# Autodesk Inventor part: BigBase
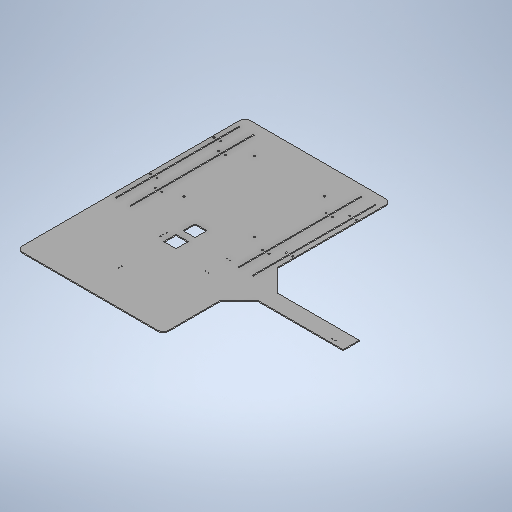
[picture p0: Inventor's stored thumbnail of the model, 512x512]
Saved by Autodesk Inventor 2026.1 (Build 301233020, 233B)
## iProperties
Created: 2026-10
Part Number: BigBase
Material: Generic
Document SubType Name: Modeling
Designer: hp
Density: 1 g/cm^3
Appearance: Default
Author: hp
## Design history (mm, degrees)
sketch "BigBaseSketch"
  geometry: L1 (0, 0)-(1200, 0); L2 (1200, 0)-(1200, 770); L3 (1200, 770)-(0, 770); L4 (0, 770)-(0, 0); L5 (150, 200)-(520, 570); L6 (520, 200)-(150, 570); C1 r 5 at (520, 200); C2 r 5 at (520, 570); C3 r 5 at (150, 200); C4 r 5 at (150, 570); 2 further points
  constraints: 12 end point, 4 centre point, 2 horizontal alignment, 2 midpoint, 2 parallel, 2 vertical alignment, 1 horizontal, 1 perpendicular
  dimensions: "d0" = 1200 distance of L3.end L2.end; "d4" = 10 diameter of C1 (= d10); "d8" = 10 diameter of C2 (= d10); "d9" = 370 distance of L5.end L6.start (= d12); "d10" = 10 diameter of C3; "d11" = 10 diameter of C4; "d12" = 370 distance of L6.end L5.start; "d13" = 370 distance of L6.end L5.end (= d9); "d39" = 200 distance from line of L5.start L1
extrude "Extrusion2" new body sketch "BigBaseSketch" distance "d14" = 5; taper "d15" = 0 deg
sketch "StorageAreaSketch"
  geometry: L1 (435, 205)-(515, 205); L2 (515, 205)-(515, 285); L3 (515, 285)-(435, 285); L4 (435, 295)-(515, 295); L5 (345, 205)-(425, 205); L6 (435, 285)-(435, 205); L7 (425, 205)-(425, 285); L8 (345, 285)-(345, 205); L9 (425, 285)-(345, 285); L10 (515, 295)-(515, 375); L11 (515, 375)-(435, 375); L12 (345, 295)-(425, 295); L13 (435, 395)-(515, 395); L14 (345, 375)-(345, 295); L15 (425, 375)-(345, 375); L16 (245, 285)-(245, 205); L17 (435, 475)-(435, 395); L18 (425, 475)-(345, 475); L19 (325, 375)-(245, 375); L20 (235, 205)-(235, 285); L21 (245, 205)-(325, 205); L22 (325, 205)-(325, 285); L23 (325, 285)-(245, 285); L24 (155, 295)-(235, 295); L25 (155, 205)-(235, 205); L26 (235, 285)-(155, 285); L27 (155, 285)-(155, 205); L28 (155, 375)-(155, 295); L29 (155, 485)-(235, 485); L30 (235, 485)-(235, 565); L31 (235, 565)-(155, 565); L32 (155, 565)-(155, 485); L33 (345, 475)-(345, 395); L34 (325, 295)-(325, 375); L35 (245, 375)-(245, 295); L36 (245, 295)-(325, 295); L37 (235, 295)-(235, 375); L38 (345, 395)-(425, 395); L39 (425, 295)-(425, 375); L40 (135, 385)-(535, 385); L41 (135, 185)-(135, 585); L42 (135, 585)-(535, 585); L43 (535, 185)-(135, 185); L44 (335, 585)-(335, 185); L45 (535, 585)-(535, 185); L46 (435, 375)-(435, 295); L47 (235, 395)-(235, 475); L48 (325, 395)-(325, 475); L49 (245, 475)-(245, 395); L50 (245, 395)-(325, 395); L51 (235, 375)-(155, 375); L52 (155, 395)-(235, 395); L53 (155, 475)-(155, 395); L54 (235, 475)-(155, 475); L55 (325, 475)-(245, 475); L56 (245, 485)-(325, 485); L57 (325, 485)-(325, 565); L58 (325, 565)-(245, 565); L59 (245, 565)-(245, 485); L60 (515, 395)-(515, 475); L61 (425, 395)-(425, 475); L62 (345, 565)-(345, 485); L63 (345, 485)-(425, 485); L64 (515, 475)-(435, 475)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; C1 r 5 at (520, 200); C2 r 5 at (150, 200); C3 r 5 at (520, 570); C4 r 5 at (150, 570); C5 r 5 at (520, 570) reference; 1 further point
  constraints: 140 end point, 4 centre point, 4 collinear, 4 horizontal, 4 midpoint, 4 parallel, 3 symmetric about line, 2 perpendicular, 2 vertical, 1 concentric, 119 other
  dimensions: "d48" = 80 distance of L31.end L30.end; "d49" = 80 distance of L30.end L29.end; "d50" = 90 distance of L29.start L52.start; "d51" = 90 distance of L29.start L56.start; "d52" = 190 distance of L29.end L24.end; "d53" = 190 distance of L29.end L63.end; "d54" = 20 distance between parallel lines of L27 L41; "d55" = 20 distance between parallel lines of L21 L43; "d56" = 20 distance between parallel lines of L10 L45; "d57" = 20 distance between parallel lines of L58 L42; "d58" = 10 diameter of C4; "d59" = 15 distance from line of L42 C4.centre (= d60); "d60" = 15 distance from line of L41 C4.centre
  node "Sketch Rectangular Pattern1" dims "d50" = 90, "d51" = 90
  node "Sketch Rectangular Pattern2" dims "d52" = 190, "d53" = 190
sketch "Sketch3"
  geometry: L1 (135, 185)-(135, 585) reference; L2 (55, 65)-(55, 705); L3 (535, 185)-(135, 185) reference; L4 (135, 585)-(535, 585) reference; L5 (135, 385)-(535, 385) reference; L6 (55, 100)-(705, 100); L7 (705, 100)-(705, 105); L8 (705, 105)-(55, 105); L9 (55, 105)-(55, 100); L10 (55, 25)-(705, 25); L11 (705, 25)-(705, 30); L12 (705, 30)-(55, 30); L13 (55, 30)-(55, 25); L14 (55, 665)-(700, 665); L15 (700, 665)-(700, 670); L16 (700, 670)-(55, 670); L17 (55, 670)-(55, 665); L18 (55, 740)-(700, 740); L19 (700, 745)-(55, 745); L20 (700, 740)-(700, 745); L21 (55, 745)-(55, 740); 3 further points
  constraints: 34 end point, 8 parallel, 4 horizontal, 4 perpendicular, 2 collinear, 2 midpoint, 1 horizontal alignment
  dimensions: "d64" = 640 distance of L2.end L2.start; "d65" = 80 distance between parallel lines of L1 L2; "d129" = 650 distance of L8.end L7.end; "d130" = 5 distance of L7.end L6.end; "d131" = 80 distance between parallel lines of L1 L9; "d132" = 80 distance between parallel lines of L8 L3; "d133" = 650 distance of L12.end L11.end (derived); "d134" = 5 distance of L11.end L10.end; "d135" = 70 distance between parallel lines of L6 L12; "d138" = 645 distance of L16.end L15.end; "d139" = 5 distance of L15.end L14.end; "d140" = 645 distance of L19.end L19.start; "d141" = 5 distance of L19.start L18.end; "d142" = 80 distance between parallel lines of L4 L14; "d143" = 80 distance between parallel lines of L17 L1; "d144" = 70 distance between parallel lines of L16 L18
extrude "Extrusion3" cut sketch "Sketch3" extent not by distance; stored distance "d101" = 0; taper "d102" = 0 deg
sketch "Sketch4"
  geometry: L1 (535, 585)-(535, 185) reference; L2 (715, 352.5)-(780, 352.5); L3 (780, 352.5)-(780, 417.5); L4 (780, 417.5)-(715, 417.5); L5 (715, 417.5)-(715, 352.5); L6 (780, 417.5)-(780, 352.5); L7 (679, 353.5)-(616, 353.5); L8 (616, 353.5)-(616, 416.5); L9 (616, 416.5)-(679, 416.5); L10 (679, 416.5)-(679, 353.5); L11 (679, 353.5)-(616, 416.5); L12 (616, 353.5)-(679, 416.5); C1 r 31.5 at (647.5, 385); 9 further points
  constraints: 22 end point, 5 midpoint, 4 parallel, 2 horizontal, 2 horizontal alignment, 2 perpendicular, 1 centre point, 1 coincident
  dimensions: "d110" = 63 diameter of C1; "d111" = 112.5 distance from line of L1 C1.centre; "d119" = 65 distance of L4.end L3.end; "d120" = 65 distance of L3.end L2.end; "d121" = 67.5 distance from line of C1.centre L5; "d145" = 63 distance of L7.end L8.end (derived); "d146" = 63 distance of L8.end L9.end (derived)
extrude "Extrusion4" cut sketch "Sketch4" extent not by distance; stored distance "d112" = 0; taper "d113" = 0 deg
fillet "Fillet1" dims "d147" = 30
sketch "Sketch5"
  geometry: L1 (715, 352.5)-(715, 417.5) reference; L2 (780, 417.5)-(780, 352.5) reference; L3 (715, 417.5)-(780, 417.5); L4 (780, 417.5)-(780, 1317.5); L5 (780, 1317.5)-(715, 1317.5); L6 (715, 1317.5)-(715, 417.5); L7 (1170, 770)-(30, 770) reference; L8 (899.316, 770)-(780, 889.316); L9 (747.5, 417.5)-(747.5, 1317.5); L10 (595.684, 770)-(715, 889.316); L11 (800, 417.5)-(800, 1317.5); L12 (800, 1317.5)-(780, 1317.5); L13 (800, 417.5)-(780, 417.5); 8 further points
  constraints: 20 end point, 2 horizontal, 2 midpoint, 2 parallel, 2 perpendicular, 2 point on line, 2 symmetric about line, 1 collinear, 1 vertical
  dimensions: "d148" = 900 distance of L4.start L4.end; "d158" = 45 deg angle of L7 L8; "d166" = 20 distance of L11.start L4.start
extrude "Extrusion5" join sketch "Sketch5" distance "d149" = 5; taper "d150" = 0 deg
sketch "Sketch6"
  geometry: 16 further points
hole "Hole1" sketch "Sketch6" at (-507.5, 10), (-172.5, 10), (-172.5, 45), (-222.5, 85), (-507.5, 45), (-557.5, 85), (-557.5, 120), (-222.5, 120), (-557.5, 650), (-557.5, 685), (-222.5, 650), (-222.5, 685)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 diameter "d151" = 9; stored, may be unused: countersink angle "d155" = 90 deg, drill point angle "d157" = 0 deg; dims "d152" = 6, "d153" = 4, "d154" = 2, "d156" = 8
sketch "Sketch7"
  geometry: 4 further points
hole "Hole2" sketch "Sketch7" at (-690, 597), (-690, 613), (-805, 597), (-805, 613) diameter "d159" = 4.5; stored, may be unused: countersink angle "d163" = 90 deg, drill point angle "d165" = 0 deg; dims "d160" = 6, "d161" = 4, "d162" = 2, "d164" = 8
sketch "Sketch8"
  geometry: 2 further points
hole "Hole3" sketch "Sketch8" at (-1002, 354), (-1018, 354) diameter "d167" = 4.5; stored, may be unused: countersink angle "d171" = 90 deg, drill point angle "d173" = 0 deg; dims "d168" = 6, "d169" = 4, "d170" = 2, "d172" = 8
sketch "Sketch9"
  geometry: 2 further points
hole "Hole4" sketch "Sketch9" at (-778.5, 1239.5), (-778.5, 1255.5) diameter "d174" = 4.5; stored, may be unused: countersink angle "d178" = 90 deg, drill point angle "d180" = 0 deg; dims "d175" = 6, "d176" = 4, "d177" = 2, "d179" = 8
sketch "Sketch10"
  geometry: 1 further point
hole "Hole5" sketch "Sketch10" at (747.987, 318.8) diameter "d181" = 3.4; stored, may be unused: countersink angle "d185" = 90 deg, drill point angle "d187" = 0 deg; dims "d182" = 6, "d183" = 4, "d184" = 2, "d186" = 8
sketch "Sketch11"
  geometry: 2 further points
hole "Hole6" sketch "Sketch11" at (764, 320), (731, 320) diameter "d188" = 5.5; stored, may be unused: countersink angle "d192" = 90 deg, drill point angle "d194" = 0 deg; dims "d189" = 6, "d190" = 4, "d191" = 2, "d193" = 8
body "Solid2"
